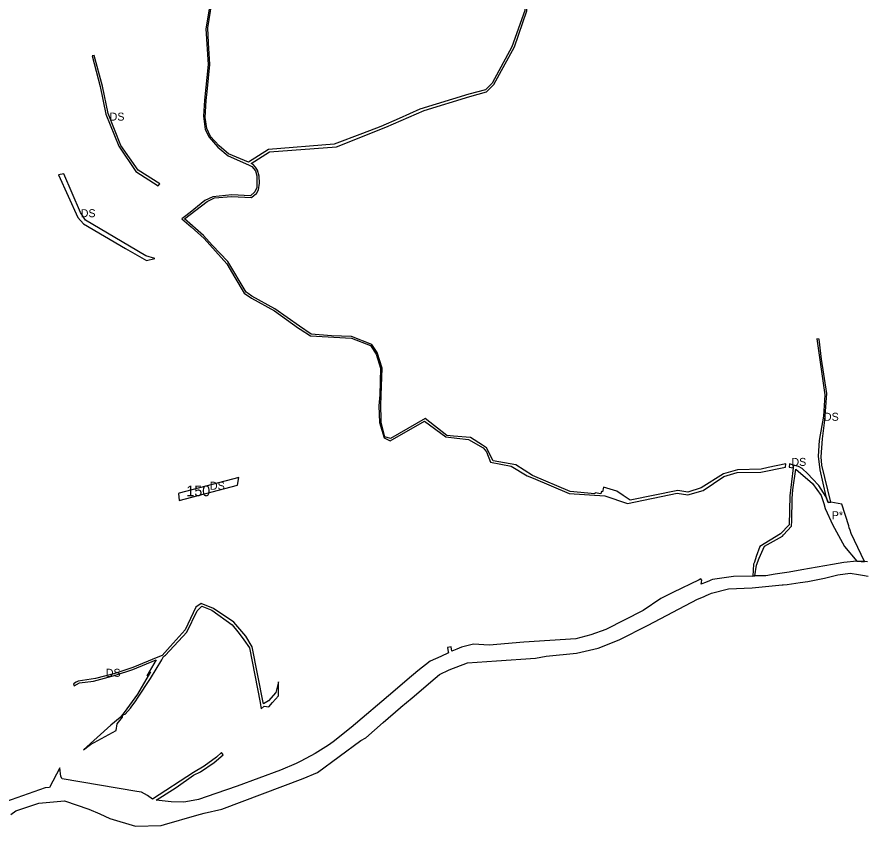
# Model space of a CAD drawing. Extents: x -477304 to -465641, y -1159113 to -1149285.
# Drawn here: x -469014 to -468059, y -1153155 to -1152244 of the extents above; entities that cross this region are included whole.
import ezdxf

# ---------------------------------------------------------------- set-up
doc = ezdxf.new("R2010")
doc.units = 0
for name, color, linetype in [('14', 7, 'Continuous'), ('34', 7, 'Continuous'), ('35', 7, 'Continuous'), ('60', 7, 'Continuous')]:
    doc.layers.add(name, color=color, linetype=linetype)

msp = doc.modelspace()

# ---------------------------------------------------------------- linework, layer by layer
at = {"layer": '14'}
for p, q in [((-468764.44, -1152762.33), (-468831.54, -1152779.89)), ((-468765.93, -1152770.99), (-468764.44, -1152762.33)), ((-468831.39, -1152788.12), (-468765.93, -1152770.99)), ((-468831.54, -1152779.89), (-468832.43, -1152780.12)), ((-468832.43, -1152780.12), (-468831.71, -1152788.2)), ((-468831.71, -1152788.2), (-468831.39, -1152788.12))]:
    msp.add_line(p, q, dxfattribs=at)
at = {"layer": '34'}
for p, q in [((-468140.7, -1152751.54), (-468144.53, -1152783.05)), ((-468141.25, -1152776.07), (-468137.84, -1152753.03)), ((-468140.29, -1152748.18), (-468140.7, -1152751.54)), ((-468137.84, -1152753.03), (-468118.97, -1152769.09)), ((-468118.96, -1152763.88), (-468124.22, -1152758.05)), ((-468118.97, -1152769.09), (-468109.21, -1152782.37)), ((-468112.02, -1152771.44), (-468118.96, -1152763.88)), ((-468104.12, -1152783.55), (-468112.02, -1152771.44)), ((-468109.21, -1152782.37), (-468106.39, -1152791.62)), ((-468101.39, -1152790.45), (-468104.12, -1152783.55)), ((-468098.34, -1152790.02), (-468101.39, -1152790.45)), ((-468086.06, -1152792.35), (-468098.34, -1152790.02)), ((-468078.35, -1152816.72), (-468086.06, -1152792.35)), ((-468151.67, -1152826.89), (-468142.79, -1152817.18)), ((-468096.28, -1152815.84), (-468094.31, -1152819.46)), ((-468094.31, -1152819.46), (-468083.24, -1152839.96)), ((-468155.05, -1152825.6), (-468178.53, -1152839.9)), ((-468152.89, -1152828.22), (-468151.67, -1152826.89)), ((-468075.66, -1152825.31), (-468076.55, -1152821.45)), ((-468060.54, -1152856.85), (-468075.66, -1152825.31)), ((-468178.53, -1152839.9), (-468182.42, -1152851.01)), ((-468083.24, -1152839.96), (-468069.07, -1152856.46)), ((-468182.42, -1152851.01), (-468184.49, -1152857.73)), ((-468182.19, -1152860.95), (-468179.28, -1152853.08)), ((-468069.07, -1152856.46), (-468064.29, -1152856.68)), ((-468064.29, -1152856.68), (-468060.54, -1152856.85)), ((-468183.92, -1152873.11), (-468182.19, -1152860.95)), ((-468186.08, -1152873.15), (-468183.92, -1152873.11))]:
    msp.add_line(p, q, dxfattribs=at)
for points in [[(-468124.22, -1152758.05), (-468130.85, -1152752.17), (-468134.76, -1152749.78), (-468140.29, -1152748.18)], [(-468142.79, -1152817.18), (-468142.26, -1152810.99), (-468141.84, -1152785.83), (-468141.25, -1152776.07)], [(-468144.53, -1152783.05), (-468145.49, -1152815.51), (-468155.05, -1152825.6)], [(-468106.39, -1152791.62), (-468104.73, -1152797.09), (-468096.28, -1152815.84)], [(-468076.55, -1152821.45), (-468077.77, -1152818.84), (-468078.35, -1152816.72)], [(-468179.28, -1152853.08), (-468173.27, -1152839.39), (-468152.89, -1152828.22)], [(-468184.49, -1152857.73), (-468185.3, -1152859.92), (-468186.08, -1152873.15)]]:
    msp.add_lwpolyline(points, dxfattribs=at)
at = {"layer": '35'}
for p, q in [((-468927.23, -1152287.18), (-468929.24, -1152287.56)), ((-468929.24, -1152287.56), (-468920.32, -1152321.98)), ((-468917.94, -1152321.66), (-468927.23, -1152287.18)), ((-468798.82, -1152297.53), (-468803.01, -1152337.62)), ((-468920.32, -1152321.98), (-468914.1, -1152353.33)), ((-468911.58, -1152352.42), (-468917.94, -1152321.66)), ((-468485.74, -1152327.99), (-468477.71, -1152320.03)), ((-468487.11, -1152325.81), (-468505.68, -1152330.94)), ((-468504.56, -1152333.51), (-468485.74, -1152327.99)), ((-468803.01, -1152337.62), (-468804.27, -1152355.55)), ((-468802.12, -1152356.87), (-468801.14, -1152337.79)), ((-468914.1, -1152353.33), (-468899.56, -1152389.47)), ((-468897.2, -1152388.73), (-468911.58, -1152352.42)), ((-468804.27, -1152355.55), (-468802.36, -1152370.38)), ((-468800.44, -1152369.43), (-468802.12, -1152356.87)), ((-468802.36, -1152370.38), (-468797.97, -1152379.35)), ((-468797.97, -1152379.35), (-468787.93, -1152390.52)), ((-468625.15, -1152375.07), (-468657.06, -1152387.14)), ((-468899.56, -1152389.47), (-468880.11, -1152417.89)), ((-468877.71, -1152416.31), (-468897.2, -1152388.73)), ((-468787.93, -1152390.52), (-468776.53, -1152400.21)), ((-468753.36, -1152407.43), (-468775.95, -1152397.97)), ((-468750.62, -1152408.68), (-468730.1, -1152395.73)), ((-468776.53, -1152400.21), (-468753.37, -1152410.26)), ((-468748.13, -1152409.88), (-468750.62, -1152408.68)), ((-468880.11, -1152417.89), (-468854.99, -1152433.91)), ((-468853.36, -1152431.81), (-468877.71, -1152416.31)), ((-468753.37, -1152410.26), (-468749.75, -1152412.25)), ((-468741.56, -1152423.03), (-468743.36, -1152416.47)), ((-468961.35, -1152420.5), (-468967.45, -1152421.76)), ((-468967.45, -1152421.76), (-468945.34, -1152469.74)), ((-468942.46, -1152464.09), (-468961.35, -1152420.5)), ((-468854.99, -1152433.91), (-468853.36, -1152431.81)), ((-468793.54, -1152446.16), (-468802.58, -1152450.55)), ((-468746.29, -1152440.57), (-468751.21, -1152445.23)), ((-468750.03, -1152447.23), (-468747.3, -1152444.6)), ((-468825.6, -1152471.07), (-468800.19, -1152451.62)), ((-468802.58, -1152450.55), (-468819.22, -1152463.9)), ((-468800.19, -1152451.62), (-468791.81, -1152447.55)), ((-468936.84, -1152472.6), (-468942.46, -1152464.09)), ((-468819.22, -1152463.9), (-468825.52, -1152468.68)), ((-468825.52, -1152468.68), (-468828.47, -1152470.92)), ((-468828.47, -1152470.92), (-468818, -1152480.15)), ((-468858.76, -1152515.92), (-468869.12, -1152512.66)), ((-468754.02, -1152555.17), (-468756.33, -1152553.46)), ((-468724.18, -1152574.66), (-468697.24, -1152594.11)), ((-468696.16, -1152592.08), (-468723.84, -1152572.52)), ((-468697.24, -1152594.11), (-468695.42, -1152595.31)), ((-468683.07, -1152601.01), (-468696.16, -1152592.08)), ((-468695.42, -1152595.31), (-468683.81, -1152602.82)), ((-468683.81, -1152602.82), (-468637.71, -1152605.51)), ((-468637.71, -1152605.51), (-468616.45, -1152613.71)), ((-468111.77, -1152606.71), (-468114.26, -1152606.34)), ((-468114.26, -1152606.34), (-468105.27, -1152669.1)), ((-468108.86, -1152629.11), (-468111.77, -1152606.71)), ((-468616.45, -1152613.71), (-468609.89, -1152623.44)), ((-468609.89, -1152623.44), (-468605.21, -1152639.34)), ((-468603.09, -1152639.16), (-468608.69, -1152621.54)), ((-468604.19, -1152669.47), (-468603.09, -1152639.16)), ((-468601.06, -1152717.65), (-468594.12, -1152721.04)), ((-468504, -1152717.33), (-468523.1, -1152715.57)), ((-468519.27, -1152717.93), (-468505.95, -1152719.32)), ((-468108.53, -1152748.49), (-468109.5, -1152739.04)), ((-468457.96, -1152749.5), (-468440.13, -1152760.19)), ((-468433.89, -1152759.87), (-468452.87, -1152748.13)), ((-468176.95, -1152752.75), (-468203.29, -1152753.69)), ((-468169, -1152751.09), (-468176.95, -1152752.75)), ((-468149.09, -1152746.69), (-468169, -1152751.09)), ((-468149.41, -1152750.51), (-468149.09, -1152746.69)), ((-468140.29, -1152748.18), (-468144.92, -1152746.84)), ((-468140.7, -1152751.54), (-468140.29, -1152748.18)), ((-468098.34, -1152790.02), (-468108.53, -1152748.49)), ((-468391.87, -1152778.18), (-468433.89, -1152759.87)), ((-468203.29, -1152753.69), (-468219.38, -1152758.24)), ((-468218.98, -1152761.22), (-468203.81, -1152756.69)), ((-468110.71, -1152753.68), (-468104.12, -1152783.55)), ((-468363.8, -1152780.78), (-468391.87, -1152778.18)), ((-468363.57, -1152779.53), (-468363.8, -1152780.78)), ((-468357.03, -1152780.75), (-468363.57, -1152779.53)), ((-468356.53, -1152778.06), (-468357.03, -1152780.75)), ((-468327.26, -1152791.65), (-468271.22, -1152779.77)), ((-468271.22, -1152779.77), (-468259.47, -1152781.84)), ((-468352.65, -1152782.94), (-468327.26, -1152791.65)), ((-468104.12, -1152783.55), (-468101.39, -1152790.45)), ((-468101.39, -1152790.45), (-468098.34, -1152790.02)), ((-468083.67, -1152857.85), (-468096.47, -1152860.14)), ((-468069.07, -1152856.46), (-468083.67, -1152857.85)), ((-468057.25, -1152857), (-468060.54, -1152856.85)), ((-468096.47, -1152860.14), (-468131.16, -1152866.33)), ((-468244.69, -1152876.41), (-468246.63, -1152877.36)), ((-468243.51, -1152877.87), (-468244.69, -1152876.41)), ((-468183.92, -1152873.11), (-468186.08, -1152873.15)), ((-468171.65, -1152872.87), (-468183.92, -1152873.11)), ((-468160.97, -1152871.24), (-468171.65, -1152872.87)), ((-468124.3, -1152879.24), (-468105.74, -1152875.57)), ((-468105.74, -1152875.57), (-468090.64, -1152871.71)), ((-468090.64, -1152871.71), (-468076.59, -1152870.01)), ((-468076.59, -1152870.01), (-468067.31, -1152871.57)), ((-468067.31, -1152871.57), (-468062.93, -1152872.3)), ((-468062.93, -1152872.3), (-468056.57, -1152873.37)), ((-468246.63, -1152877.36), (-468276.2, -1152891.8)), ((-468244.34, -1152882.27), (-468243.51, -1152877.87)), ((-468213.65, -1152887.69), (-468187.1, -1152886.35)), ((-468187.1, -1152886.35), (-468153.13, -1152883.17)), ((-468153.13, -1152883.17), (-468152.22, -1152883.08)), ((-468152.22, -1152883.08), (-468147.45, -1152882.7)), ((-468147.45, -1152882.7), (-468133.13, -1152880.55)), ((-468133.13, -1152880.55), (-468124.3, -1152879.24)), ((-468241.83, -1152896.48), (-468238.82, -1152895.17)), ((-468238.82, -1152895.17), (-468236.11, -1152893.98)), ((-468236.11, -1152893.98), (-468232.9, -1152892.59)), ((-468232.9, -1152892.59), (-468213.65, -1152887.69)), ((-468304.04, -1152928.53), (-468248.43, -1152899.36)), ((-468248.43, -1152899.36), (-468241.83, -1152896.48)), ((-468823.04, -1152936.51), (-468811.38, -1152912.18)), ((-468769.89, -1152925.15), (-468792.84, -1152909.73)), ((-468824.74, -1152933.67), (-468841.63, -1152952.44)), ((-468756.67, -1152941.02), (-468769.89, -1152925.15)), ((-468336.58, -1152945.07), (-468304.04, -1152928.53)), ((-468765.51, -1152936.09), (-468761.81, -1152940.68)), ((-468761.81, -1152940.68), (-468758.89, -1152944.9)), ((-468749.47, -1152952.72), (-468756.67, -1152941.02)), ((-468841.63, -1152952.44), (-468850.75, -1152962.58)), ((-468758.89, -1152944.9), (-468752.5, -1152954.15)), ((-468736.95, -1153015.34), (-468749.47, -1152952.72)), ((-468524.83, -1152957.9), (-468525.52, -1152952.95)), ((-468360.33, -1152954.46), (-468336.58, -1152945.07)), ((-468850.75, -1152962.58), (-468855.54, -1152964.33)), ((-468528.69, -1152959.69), (-468537.11, -1152963.6)), ((-468528.91, -1152958.47), (-468528.69, -1152959.69)), ((-468519.03, -1152955.34), (-468524.83, -1152957.9)), ((-468883.72, -1152978.42), (-468857.28, -1152967.29)), ((-468857.28, -1152967.29), (-468868.08, -1152985.59)), ((-468863.71, -1152988.51), (-468851.1, -1152967.47)), ((-468851.1, -1152967.47), (-468849.03, -1152963.82)), ((-468549.03, -1152969.13), (-468563.23, -1152979.99)), ((-468537.11, -1152963.6), (-468549.03, -1152969.13)), ((-468527.96, -1152978.57), (-468507.3, -1152970.85)), ((-468507.3, -1152970.85), (-468474.45, -1152968.64)), ((-468474.45, -1152968.64), (-468430.77, -1152965.71)), ((-468430.77, -1152965.71), (-468418.88, -1152963.52)), ((-468868.08, -1152985.59), (-468863.76, -1152981.04)), ((-468563.23, -1152979.99), (-468574.94, -1152989.95)), ((-468538.54, -1152983.89), (-468527.96, -1152978.57)), ((-468943.8, -1152993.23), (-468928.03, -1152991.63)), ((-468928.03, -1152991.63), (-468919.73, -1152989.12)), ((-468878.29, -1153010.72), (-468863.71, -1152988.51)), ((-468574.94, -1152989.95), (-468591.2, -1153003.79)), ((-468949.5, -1152996.62), (-468943.8, -1152993.23)), ((-468719.73, -1153007.93), (-468719.84, -1152992.06)), ((-468726.5, -1153015.54), (-468719.73, -1153007.93)), ((-468591.2, -1153003.79), (-468638.08, -1153043.69)), ((-468582.06, -1153020.81), (-468569.56, -1153010.16)), ((-468740.09, -1153018.31), (-468739.39, -1153022.76)), ((-468739.39, -1153022.76), (-468736.08, -1153019.68)), ((-468736.64, -1153016.9), (-468736.95, -1153015.34)), ((-468736.08, -1153019.68), (-468730.79, -1153020.36)), ((-468730.79, -1153020.36), (-468726.5, -1153015.54)), ((-468895.19, -1153031.99), (-468894.98, -1153029.42)), ((-468601.99, -1153038.14), (-468582.61, -1153021.28)), ((-468582.61, -1153021.28), (-468582.06, -1153020.81)), ((-468901.4, -1153039.49), (-468895.19, -1153031.99)), ((-468621.54, -1153055.14), (-468601.99, -1153038.14)), ((-468638.08, -1153043.69), (-468658.33, -1153059.61)), ((-468675.76, -1153094.22), (-468627.15, -1153058.22)), ((-468627.15, -1153058.22), (-468621.54, -1153055.14)), ((-468939.13, -1153068.94), (-468931.22, -1153062.78)), ((-468663.55, -1153063.71), (-468678.67, -1153072.98)), ((-468658.33, -1153059.61), (-468663.55, -1153063.71)), ((-468783.8, -1153071.94), (-468789.51, -1153077.17)), ((-468781.9, -1153074.33), (-468783.8, -1153071.94)), ((-468678.67, -1153072.98), (-468694.74, -1153081.42)), ((-468694.74, -1153081.42), (-468700.07, -1153084.22)), ((-468815.27, -1153097.32), (-468807.53, -1153093.41)), ((-468692.14, -1153101.23), (-468675.76, -1153094.22)), ((-468879.08, -1153115.62), (-468963.08, -1153101.51)), ((-468835, -1153111.21), (-468815.27, -1153097.32)), ((-468783.49, -1153135.47), (-468692.14, -1153101.23)), ((-468873.99, -1153116.48), (-468879.08, -1153115.62)), ((-468857.3, -1153125.4), (-468835, -1153111.21)), ((-468867.28, -1153120.12), (-468873.99, -1153116.48)), ((-468861.45, -1153124.19), (-468867.28, -1153120.12)), ((-468932.99, -1153135.46), (-468920.93, -1153140.87)), ((-468920.93, -1153140.87), (-468909.62, -1153145.94)), ((-468848.21, -1153152.77), (-468811.63, -1153142.19)), ((-468811.63, -1153142.19), (-468803.26, -1153140.22)), ((-468803.26, -1153140.22), (-468783.49, -1153135.47)), ((-468851.69, -1153153.78), (-468848.21, -1153152.77))]:
    msp.add_line(p, q, dxfattribs=at)
for points in [[(-468796.95, -1152297.47), (-468798.67, -1152272.99), (-468799.28, -1152256.03), (-468792.77, -1152216.04), (-468804.96, -1152182.43), (-468804.75, -1152166.24)], [(-468477.71, -1152320.03), (-468454.22, -1152277.51), (-468440.48, -1152236.86), (-468435.07, -1152164.85), (-468437.35, -1152162.61), (-468442.58, -1152236.46), (-468457.36, -1152277.53)], [(-468807.14, -1152183.38), (-468794.61, -1152216.69), (-468801.64, -1152257.19), (-468798.82, -1152297.53)], [(-468457.36, -1152277.53), (-468479.48, -1152318.43), (-468487.11, -1152325.81)], [(-468801.14, -1152337.79), (-468800.06, -1152328.29), (-468796.95, -1152297.47)], [(-468505.68, -1152330.94), (-468560.64, -1152347.57), (-468584.12, -1152358.23)], [(-468599.03, -1152367.94), (-468555.93, -1152349.19), (-468504.56, -1152333.51)], [(-468584.12, -1152358.23), (-468604.81, -1152367.15), (-468625.15, -1152375.07)], [(-468775.95, -1152397.97), (-468786.57, -1152388.85), (-468796.29, -1152378.27), (-468800.44, -1152369.43)], [(-468730.1, -1152395.73), (-468654.63, -1152390), (-468599.03, -1152367.94)], [(-468657.06, -1152387.14), (-468731.05, -1152393.04), (-468753.36, -1152407.43)], [(-468749.75, -1152412.25), (-468745.76, -1152417.17), (-468744.3, -1152422.89)], [(-468743.36, -1152416.47), (-468745.64, -1152412.82), (-468748.13, -1152409.88)], [(-468744.3, -1152422.89), (-468744.1, -1152435.65), (-468746.29, -1152440.57)], [(-468742.2, -1152438.54), (-468741.19, -1152431.12), (-468741.56, -1152423.03)], [(-468751.21, -1152445.23), (-468772.14, -1152444.23), (-468793.54, -1152446.16)], [(-468791.81, -1152447.55), (-468772.49, -1152446.03), (-468750.03, -1152447.23)], [(-468747.3, -1152444.6), (-468744.71, -1152442.64), (-468742.2, -1152438.54)], [(-468945.34, -1152469.74), (-468939.33, -1152476.59), (-468891.96, -1152504.65)], [(-468869.12, -1152512.66), (-468887.41, -1152501.82), (-468936.84, -1152472.6)], [(-468794.37, -1152500.76), (-468804.22, -1152489.91), (-468825.6, -1152471.07)], [(-468818, -1152480.15), (-468803.31, -1152493.14), (-468778.08, -1152521.89), (-468769.05, -1152537.02)], [(-468891.96, -1152504.65), (-468868.36, -1152518.05), (-468858.76, -1152515.92)], [(-468756.33, -1152553.46), (-468776.8, -1152519.13), (-468794.37, -1152500.76)], [(-468769.05, -1152537.02), (-468758.39, -1152554.77), (-468750.22, -1152560.5), (-468724.18, -1152574.66)], [(-468723.84, -1152572.52), (-468749.96, -1152558.22), (-468754.02, -1152555.17)], [(-468637.81, -1152603.59), (-468660.18, -1152602.73), (-468683.07, -1152601.01)], [(-468608.69, -1152621.54), (-468614.75, -1152612.6), (-468637.81, -1152603.59)], [(-468105.3, -1152697.74), (-468103.15, -1152667.77), (-468108.86, -1152629.11)], [(-468605.21, -1152639.34), (-468605.79, -1152669.35), (-468606.84, -1152681.73), (-468606.26, -1152700.31), (-468601.06, -1152717.65)], [(-468604.16, -1152696.28), (-468604.68, -1152681.73), (-468604.19, -1152669.47)], [(-468105.27, -1152669.1), (-468106.9, -1152693.12), (-468111.58, -1152720.66), (-468112.87, -1152738.09), (-468110.71, -1152753.68)], [(-468600.02, -1152716.3), (-468604.12, -1152700.35), (-468604.16, -1152696.28)], [(-468523.1, -1152715.57), (-468530.49, -1152714.79), (-468554.93, -1152695.87), (-468593.72, -1152718.45), (-468600.02, -1152716.3)], [(-468594.12, -1152721.04), (-468555.46, -1152698.67), (-468531.73, -1152716.62), (-468519.27, -1152717.93)], [(-468109.5, -1152739.04), (-468107.93, -1152718.79), (-468105.3, -1152697.74)], [(-468505.95, -1152719.32), (-468489.51, -1152728.74), (-468485.83, -1152733.54), (-468481.21, -1152744.95), (-468457.96, -1152749.5)], [(-468485.83, -1152729.03), (-468490.43, -1152725.74), (-468504, -1152717.33)], [(-468452.87, -1152748.13), (-468478.43, -1152743.58), (-468485.83, -1152729.03)], [(-468203.81, -1152756.69), (-468177.35, -1152756.19), (-468149.41, -1152750.51)], [(-468144.92, -1152746.84), (-468145.39, -1152750.72), (-468140.7, -1152751.54)], [(-468440.13, -1152760.19), (-468433.24, -1152763.08), (-468392.88, -1152780.34), (-468352.65, -1152782.94)], [(-468219.38, -1152758.24), (-468244.35, -1152773.81), (-468259.49, -1152778.72), (-468270.71, -1152777.02)], [(-468259.47, -1152781.84), (-468241.97, -1152776.71), (-468218.98, -1152761.22)], [(-468354.31, -1152773.22), (-468355.25, -1152778.29), (-468356.53, -1152778.06)], [(-468270.71, -1152777.02), (-468324.15, -1152787.75), (-468331.97, -1152782.54), (-468339.3, -1152777.67), (-468354.31, -1152773.22)], [(-468060.54, -1152856.85), (-468064.29, -1152856.68), (-468069.07, -1152856.46)], [(-468131.16, -1152866.33), (-468145.45, -1152868.86), (-468160.97, -1152871.24)], [(-468186.08, -1152873.15), (-468207.78, -1152873.58), (-468231.42, -1152877.05), (-468233.3, -1152877.81)], [(-468239.34, -1152880.27), (-468243.7, -1152882.01), (-468244.34, -1152882.27)], [(-468233.3, -1152877.81), (-468235.1, -1152878.54), (-468239.34, -1152880.27)], [(-468276.2, -1152891.8), (-468289.61, -1152898.35), (-468309.59, -1152912.08), (-468351.71, -1152933.37), (-468368.47, -1152939.28), (-468385.4, -1152943.77)], [(-468792.84, -1152909.73), (-468806.72, -1152904.17), (-468812.63, -1152908.3), (-468824.74, -1152933.67)], [(-468811.38, -1152912.18), (-468806.18, -1152907.09), (-468794.66, -1152911.76)], [(-468794.66, -1152911.76), (-468772.1, -1152927.93), (-468765.51, -1152936.09)], [(-468849.03, -1152963.82), (-468846.99, -1152962.13), (-468823.04, -1152936.51)], [(-468385.4, -1152943.77), (-468443.98, -1152947.69), (-468482.73, -1152951.08)], [(-468525.52, -1152952.95), (-468529.6, -1152953.52), (-468528.91, -1152958.47)], [(-468482.73, -1152951.08), (-468500.36, -1152949.79), (-468513.94, -1152953.09), (-468519.03, -1152955.34)], [(-468752.5, -1152954.15), (-468740.56, -1153015.38), (-468740.09, -1153018.31)], [(-468418.88, -1152963.52), (-468384.42, -1152960.12), (-468360.33, -1152954.46)], [(-468855.54, -1152964.33), (-468883.81, -1152976.22), (-468903.74, -1152982.78), (-468925.61, -1152988.62)], [(-468919.73, -1152989.12), (-468903.22, -1152984.62), (-468883.72, -1152978.42)], [(-468863.76, -1152981.04), (-468878.39, -1153006.28), (-468893.47, -1153026.76), (-468897.89, -1153032.22)], [(-468925.61, -1152988.62), (-468945.33, -1152991.54), (-468947.5, -1152992.57)], [(-468569.56, -1153010.16), (-468543.57, -1152988.01), (-468538.54, -1152983.89)], [(-468947.5, -1152992.57), (-468950.49, -1152994.55), (-468949.5, -1152996.62)], [(-468719.84, -1152992.06), (-468722.78, -1153004.12), (-468731.2, -1153013.68), (-468736.64, -1153016.9)], [(-468894.98, -1153029.42), (-468892.1, -1153028.57), (-468886.12, -1153021.95), (-468885.39, -1153020.91), (-468880.23, -1153013.67), (-468878.29, -1153010.72)], [(-468897.89, -1153032.22), (-468908.22, -1153041.08), (-468939.13, -1153068.94)], [(-468931.22, -1153062.78), (-468902.48, -1153047.06), (-468901.4, -1153039.49)], [(-468789.51, -1153077.17), (-468803.39, -1153087.34), (-468815.23, -1153094.16), (-468861.45, -1153124.19)], [(-468807.53, -1153093.41), (-468792.02, -1153082.96), (-468781.9, -1153074.33)], [(-468700.07, -1153084.22), (-468717.42, -1153091.84), (-468766.38, -1153109.74), (-468790.33, -1153117.91)], [(-468963.08, -1153101.51), (-468964.59, -1153098.79), (-468965.65, -1153089.21), (-468977.31, -1153111.08)], [(-468977.31, -1153111.08), (-468982.2, -1153111.42), (-469059.21, -1153138.42), (-469067.9, -1153141.47)], [(-468824.12, -1153127.18), (-468826.45, -1153127.61), (-468840.69, -1153127.4), (-468857.3, -1153125.4)], [(-468790.33, -1153117.91), (-468809.91, -1153124.59), (-468824.12, -1153127.18)], [(-469020.86, -1153141.63), (-469015.33, -1153137.55), (-468989.21, -1153128.8)], [(-468989.21, -1153128.8), (-468960.66, -1153126.09), (-468932.99, -1153135.46)], [(-468909.62, -1153145.94), (-468880.61, -1153154.54), (-468851.69, -1153153.78)]]:
    msp.add_lwpolyline(points, dxfattribs=at)

# ---------------------------------------------------------------- texts
at = {"layer": '14'}
msp.add_text('DS', height=9, dxfattribs=at).set_placement((-468796.97, -1152776.03))
at = {"layer": '34'}
msp.add_text('P*', height=9, dxfattribs=at).set_placement((-468097.44, -1152809.25))
at = {"layer": '35'}
for p in [(-468909.78, -1152360.55), (-468942.3, -1152469.28), (-468106.3, -1152698.4), (-468142.84, -1152749.19), (-468914.1, -1152986.55)]:
    msp.add_text('DS', height=9, dxfattribs=at).set_placement(p)
at = {"layer": '60'}
msp.add_text('150', height=12, dxfattribs=at).set_placement((-468823.45, -1152783.31))

doc.saveas('drawing.dxf')
